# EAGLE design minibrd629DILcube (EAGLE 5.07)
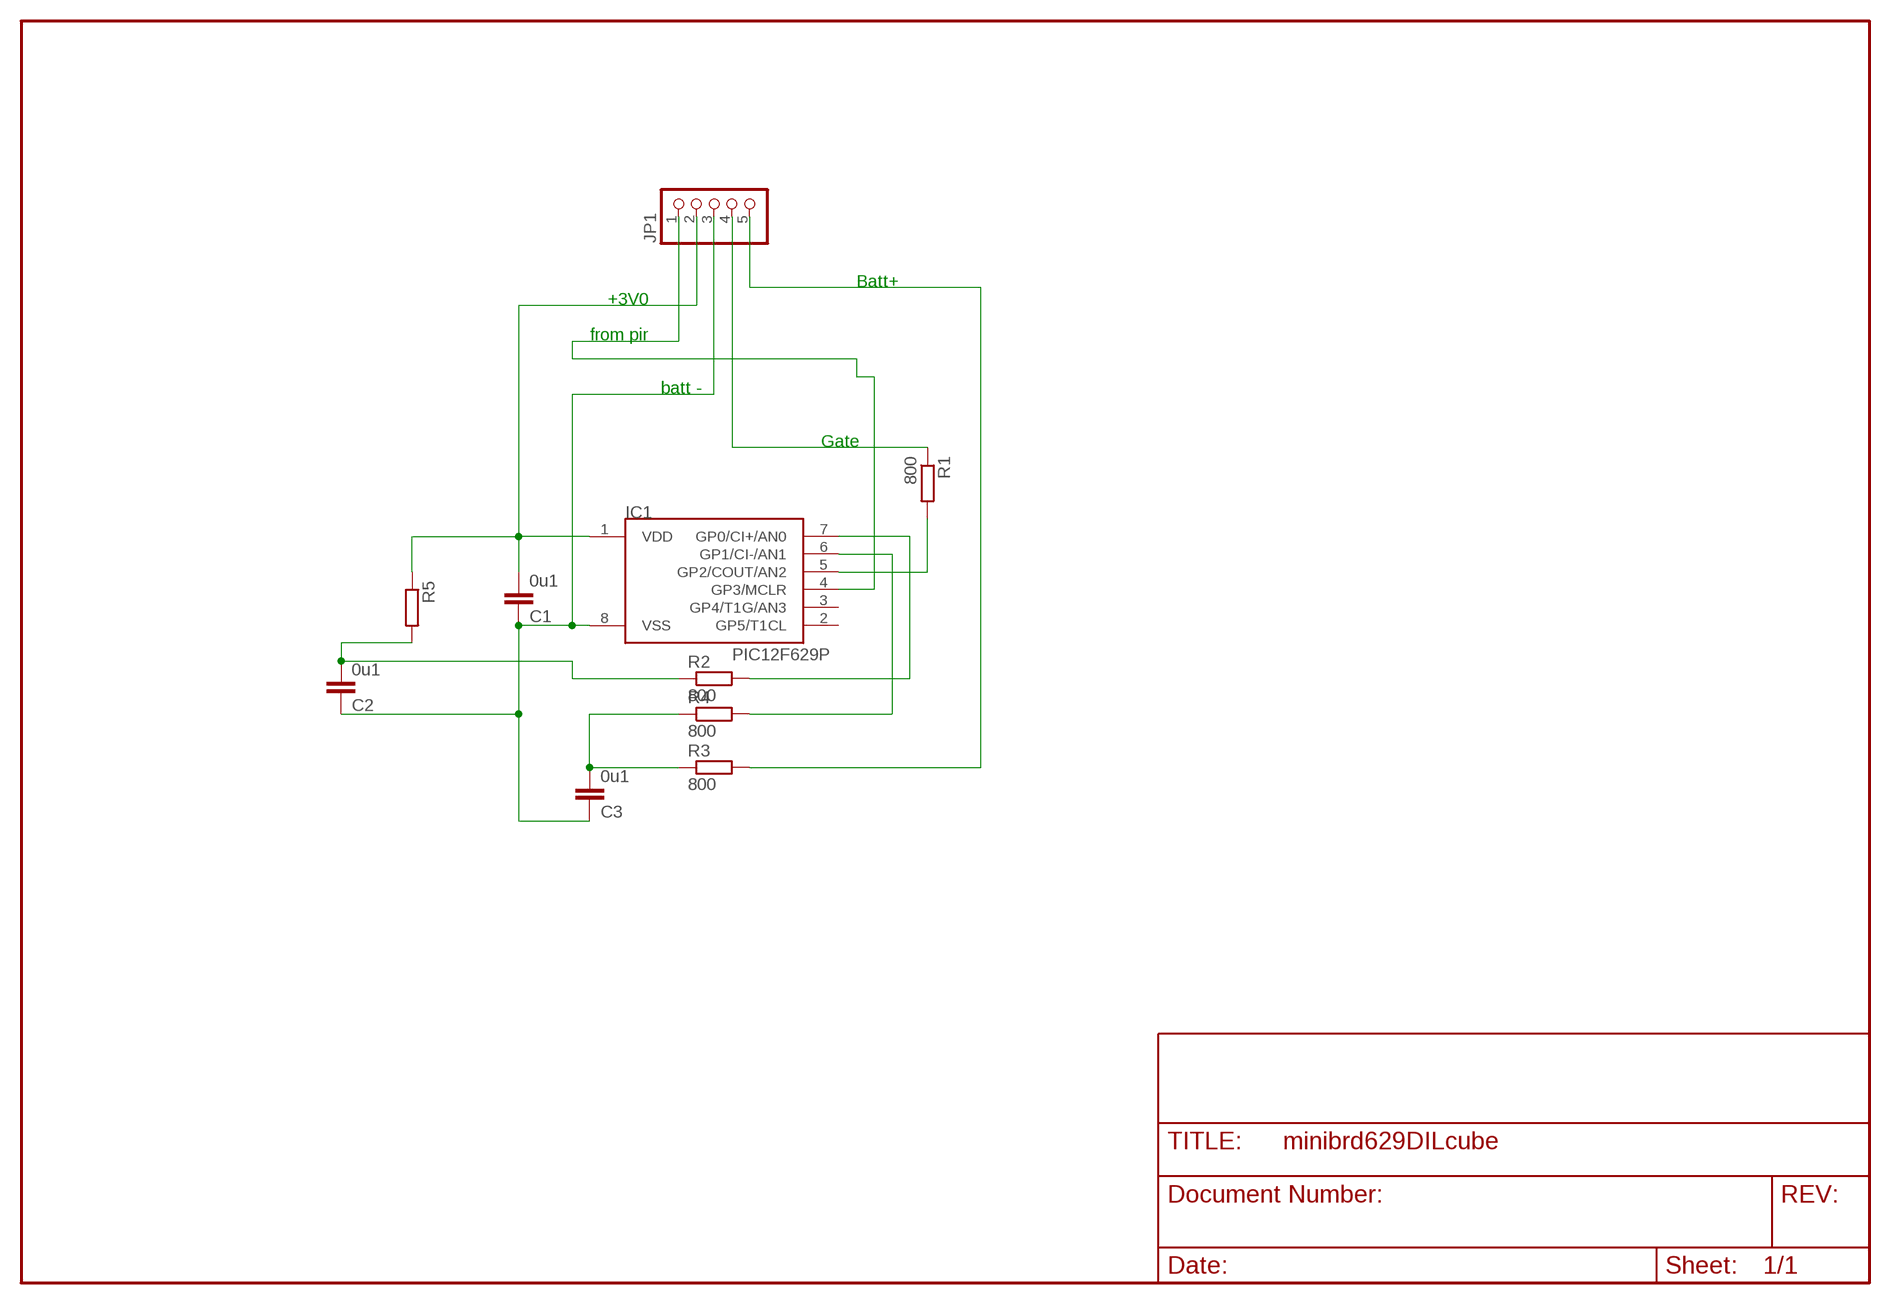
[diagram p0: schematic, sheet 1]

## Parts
C1  0u1  C-EUC1206  [C1206]
C2  0u1  C-EUC1206  [C1206]
C3  0u1  C-EUC1206  [C1206]
IC1  PIC12F629P  [DIL8]
JP1  PINHD-1X5  [1X05]
R1  800  R-EU_R1206  [R1206]
R2  800  R-EU_R1206  [R1206]
R3  800  R-EU_R1206  [R1206]
R4  800  R-EU_R1206  [R1206]
R5  R-EU_0613/5V  [P0613V]

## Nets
GATE: JP1.4 R1.1
N$1: IC1.5(GP2/COUT/AN2) R1.2
N$4: IC1.7(GP0/CI+/AN0) R2.2
N$7: C3.2 R3.1 R4.1
N$8: IC1.6(GP1/CI-/AN1) R4.2
N$9: C2.2 R2.1 R5.2
PIR: IC1.4(GP3/MCLR) JP1.1
V3: C1.2 IC1.1(VDD) JP1.2 R5.1
V+: JP1.5 R3.2
V-: C1.1 C2.1 C3.1 IC1.8(VSS) JP1.3
Unconnected: IC1.2(GP5/T1CL) IC1.3(GP4/T1G/AN3)

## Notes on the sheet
- Batt+
- +3V0
- from pir
- batt -
- Gate

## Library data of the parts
C1-C3 = rcl:C-EU: CAPACITOR, European symbol
IC1 = microchip-3:PIC12F6*: uPC nW 1k Program Flash memory 2x Timer Comparator 10b A/D converter/ 4xIN
JP1 = pinhead:PINHD-1X5: PIN HEADER
R1-R5 = rcl:R-EU_: RESISTOR, European symbol

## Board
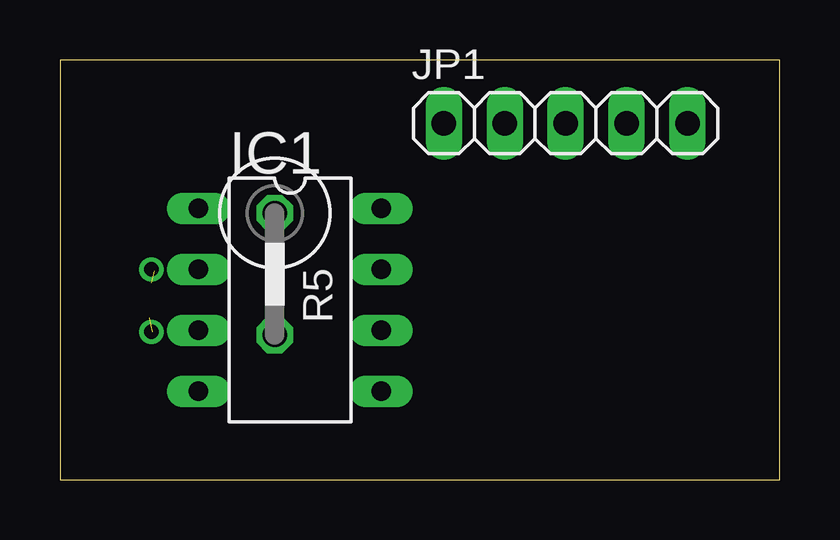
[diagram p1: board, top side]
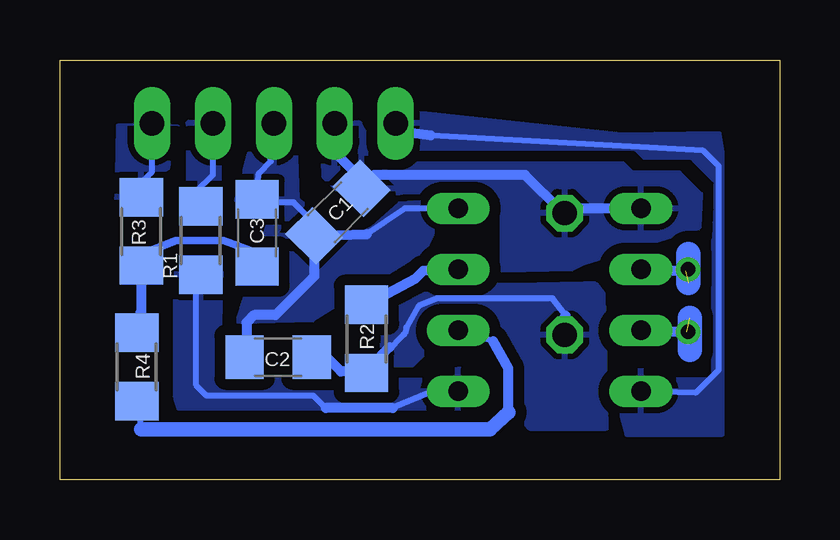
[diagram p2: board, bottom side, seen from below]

Size 30 x 17.5 mm. Coordinates in mm from the lower left corner, seen from the top.
Outline: 0,0 30,0 30,17.5 0,17.5 0,0
Copper layers (1*16): Top 0.035mm / dielectric 1.5mm / Bottom 0.035mm
Design rules "default": minimum track width 10mil, minimum drill 24mil, track to track 18mil, track to pad 18mil, pad to pad 8mil, via to via 8mil, smd to smd 8mil, copper to edge 1mil, drill to drill 8mil, minimum pad ring 10mil, minimum via ring 8mil, stop-mask expansion 4mil, vias tented up to drill 0mil, thermal gap 10mil

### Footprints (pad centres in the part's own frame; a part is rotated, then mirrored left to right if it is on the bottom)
C1206 = smd 1.6 x 1.8: 1 -1.4,0; 2 1.4,0
DIL8 = drill 0.813 long: 1 -3.81,-3.81; 2 -1.27,-3.81; 3 1.27,-3.81; 4 3.81,-3.81; 5 3.81,3.81; 6 1.27,3.81; 7 -1.27,3.81; 8 -3.81,3.81
1X05 = drill 1.016 long: 1 -5.08,0; 2 -2.54,0; 3 0,0; 4 2.54,0; 5 5.08,0
R1206 = smd 1.6 x 1.803: 1 -1.422,0; 2 1.422,0
P0613V = drill 1.016 octagon: 1 -2.54,0; 2 2.54,0

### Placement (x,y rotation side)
C1  18.41,11.16 45 bottom
C2  20.9,5.11 0 bottom
C3  21.78,10.29 270 bottom
IC1  9.59,7.49 270 top
JP1  21.08,14.86 0 top
R1  24.13,9.97 270 bottom
R2  17.22,5.87 90 bottom
R3  26.61,10.35 90 bottom
R4  26.8,4.7 270 bottom
R5  8.95,8.57 270 top

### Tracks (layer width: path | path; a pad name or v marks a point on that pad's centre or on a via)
GATE
  Bottom 0.254: JP1.4 23.62,12.7 24.32,12 24.32,11.3 24.23,11.39 R1.1
  pour Bottom (isolate 0.406): 23.37,14.92 24.57,14.92 24.64,14.86 24.64,12.45 24.77,12.32 23.5,12.32 23.37,12.45
N$1
  Bottom 0.254: IC1.5 14.61,3.62 16.13,2.98 | R1.2 23.81,8.57 24.32,8.06 24.32,3.94 23.88,3.49 19.43,3.49 18.92,2.98
  Bottom 0.406: 16.13,2.98 18.92,2.98
  pour Bottom (isolate 0.406): 13.72,4.57 12.83,4.64 12.26,4.57 12.26,2.98 25.02,2.98 25.15,3.43 25.15,9.21 25.02,9.33 23.3,9.33 23.3,8.7 23.43,4.45 21.97,4.13 14.92,4.13 14.73,4.32 13.97,4.32
N$2  (via drill 0.6)
  other vias: 3.81,6.16
N$3  (via drill 0.6)
  other vias: 3.81,8.76
N$4
  Bottom 0.406: R2.2 15.19,8.37 14.86,8.7 IC1.7
N$5  (1 unrouted)
  Bottom 0.406: 3.87,6.16 5.78,6.16
  Bottom 1.016: 3.75,6.73 3.75,5.4
N$6  (1 unrouted)
  Bottom 0.406: 3.94,8.7 5.71,8.7 5.71,8.76
  Bottom 1.016: 3.81,9.4 3.81,8.19
N$7
  Bottom 0.254: C3.2 21.65,9.4 | 26.73,9.34 26.71,9.31 R3.1 | R4.1 26.73,6.99 26.67,6.92 26.61,6.99
  Bottom 0.305: 21.65,9.4 23.18,9.97 25.15,9.97 26.73,9.34
  Bottom 0.406: R3.1 26.61,6.99
N$8
  Bottom 0.254: R4.2 26.73,3.94 26.61,2.1 | 11.94,5.78 IC1.6
  Bottom 0.406: 11.3,2.79 11.3,4.64 11.94,5.78
  Bottom 0.61: 26.61,2.1 12.06,2.1 11.3,2.79
N$9
  Bottom 0.254: 8.83,6.73 8.91,6.83 9.46,7.56 14.29,7.56 15.05,7.24 15.56,6.35 15.62,6.1 | 15.62,6.1 15.68,6.03 | 15.62,6.1 R2.1 | 17.96,4.94 17.78,4.76 17.02,4.76
  Bottom 0.305: R2.1 16.25,5.53
  Bottom 0.406: 16.25,5.53 17.02,4.76 | C2.2 18.89,5.11 18.29,4.51 17.27,4.51 17.22,4.56 | 17.22,4.56 17.21,4.57 | R2.1 17.22,4.56 | 8.91,6.83 8.92,6.83 8.95,6.79 R5.2
  pour Bottom (isolate 0.406, rank 2): 7.24,2.16 7.37,7.75 7.68,8.13 14.8,8.19 14.92,8.06 15.11,8.06 16.51,6.67 16.51,5.65 16.89,5.27 16.89,5.08 16.32,4.51 15.62,4.51 14.92,5.21 14.92,6.86 14.73,7.18 10.41,2.16
PIR
  Bottom 0.254: IC1.4 3.49,3.62 2.54,4.57 2.54,13.08 3.17,13.72 14.54,14.35 | 16,14.54 JP1.1
  Bottom 0.406: 14.54,14.35 16,14.54
  pour Bottom (isolate 0.406, rank 2): 4.25,4.51 6.03,4.51 6.6,3.94 6.6,2.79 6.35,1.91 2.41,1.91 2.41,13.65 2.54,14.41 6.6,14.35 16.07,15.37 16.57,14.29 16.57,14.16 15.49,13.08 14.48,13.08 9.4,13.4 4.32,13.4 2.73,12.19 2.73,4.25 2.98,4.13 4.25,4.13 4.45,4.32
V3
  Bottom 0.406: 9.08,11.18 9.02,11.11 R5.1 | IC1.1 8.95,11.3 9.08,11.18 | 9.08,11.18 10.6,12.7 16.83,12.7 | C1.2 17.38,12.14 16.83,12.7 | 16.83,12.7 16.89,12.7 17.46,12.13 17.46,12.57 18.73,13.84 18.73,14.73 18.61,14.86 JP1.2
  pour Bottom (isolate 0.406): 3.62,10.48 3.37,10.54 3.3,11.87 4.19,12.76 6.16,12.76 6.54,13.14 15.11,13.14 15.62,13.02 16.64,13.21 17.53,14.86 19.05,14.67 18.99,12.64 17.84,11.56 17.4,11.49 11.56,11.87 11.56,8.76 8.64,8.83 8.13,9.08
V+
  Bottom 0.254: R3.2 26.63,12.15 26.73,12.26 26.16,12.83 JP1.5
  pour Bottom (isolate 0.406): 25.08,14.67 27.56,14.73 27.62,11.75 25.53,13.02
V-
  Bottom 0.254: C3.1 21.72,12.76 21.21,13.27 21.21,14.8 21.14,14.86 JP1.3 | C3.1 21.02,11.37 | IC1.8 15.62,11.3 17.21,10.22 | 19.05,10.16 C1.1 19.4,10.7 20.26,11.56 21.34,11.56 21.4,11.49 21.59,11.69 C3.1
  Bottom 0.406: 17.21,10.22 19.05,10.16 | C1.1 19.4,8.47 21.02,6.86 21.91,6.86 22.23,6.54 22.23,5.46 22.3,5.38 C2.1
  pour Bottom (isolate 0.406): 14.16,11.62 14.03,11.3 14.8,9.59 19.49,6.67 22.54,6.6 21.08,11.3 22.29,11.3 22.61,11.62 21.97,13.97 20.26,13.91 20.19,13.46 20.13,11.68 19.3,11.05 18.1,9.97 16.95,10.48 15.81,11.49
